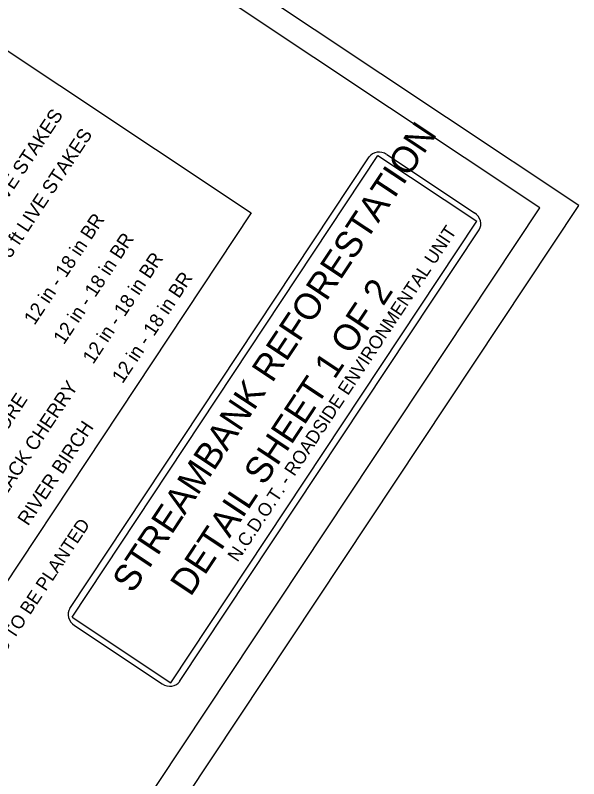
# Model space of a CAD drawing. Extents: x 561231 to 564935, y 589159 to 602519.
# Drawn here: x 564689.6 to 564935, y 589750.5 to 590082.6 of the extents above; entities that cross this region are included whole.
import ezdxf

# ---------------------------------------------------------------- set-up
doc = ezdxf.new("R2010")
doc.units = 0
doc.layers.add('Old_Level_1', color=7, linetype='Continuous')
doc.layers.add('Sheet Plot Border Outside CELL', color=7, linetype='Continuous')

msp = doc.modelspace()

# ---------------------------------------------------------------- linework, layer by layer
at = {"layer": 'Old_Level_1'}
for p, q in [((564713.43, 589824.47), (564843.78, 590021.03)), ((564714.42, 589820.79), (564847.56, 590021.55)), ((564847.56, 590021.55), (564890.57, 589993.01)), ((564851.35, 590022.07), (564889.58, 589996.7)), ((564757.43, 589792.25), (564890.57, 589993.01)), ((564761.21, 589792.77), (564891.57, 589989.32)), ((564714.42, 589820.79), (564757.43, 589792.25)), ((564715.41, 589817.1), (564753.64, 589791.73))]:
    msp.add_line(p, q, dxfattribs=at)
for points in [[(564393.35, 590347.54), (563895.29, 589597.92), (564420.03, 589249.27), (564918.09, 589998.9)], [(564487.49, 589808.73), (564667.22, 590079.74), (564792.37, 589996.71), (564612.64, 589725.7)]]:
    msp.add_lwpolyline(points, close=True, dxfattribs=at)
for centre, major_axis, start_param, end_param in [((564848.56, 590017.86), (-4.78, 3.17), 4.713138, 6.283935), ((564886.79, 589992.49), (-4.78, 3.17), 3.142342, 4.713138), ((564718.2, 589821.3), (-4.78, 3.17), 0.000749, 1.571546), ((564756.44, 589795.94), (4.78, -3.17), 4.713138, 6.283935)]:
    msp.add_ellipse(centre, major_axis=major_axis, ratio=0.880425, start_param=start_param, end_param=end_param, dxfattribs=at)
at = {"layer": 'Sheet Plot Border Outside CELL'}
msp.add_lwpolyline([(564375.99, 589158.59), (564934.98, 589999.92), (564387.75, 590363.51), (563828.77, 589522.18)], close=True, dxfattribs=at)

# ---------------------------------------------------------------- texts
at = {"layer": 'Old_Level_1'}
for s, height, rotation, p in [('2 ft - 3 ft LIVE STAKES', 6.0385, 56.4482, (564664.54, 589969.7)), ('STREAMBANK REFORESTATION', 11.4695, 56.4482, (564740.74, 589830.7)), ('2 ft - 3 ft LIVE STAKES', 6.0385, 56.4482, (564677.32, 589961.23)), ('12 in - 18 in BR', 6.0385, 56.4482, (564698.01, 589947.46)), ('N.C.D.O.T. - ROADSIDE ENVIRONMENTAL UNIT', 5.735, 56.4482, (564786.42, 589844.43)), ('12 in - 18 in BR', 6.0385, 56.4482, (564710.79, 589938.99)), ('12 in - 18 in BR', 6.0385, 56.4482, (564723.56, 589930.51)), ('12 in - 18 in BR', 6.0385, 56.4482, (564736.34, 589922.04)), ('   DETAIL SHEET 1 OF 2', 11.4695, 56.4482, (564758.91, 589818.66)), ('BLACK CHERRY', 6.0385, 56.3995, (564682.43, 589868.61)), ('SYCAMORE', 6.039, 56.3995, (564669.67, 589877.1)), ('RIVER BIRCH', 6.0385, 56.3995, (564695.2, 589860.13)), ('SEE PLAN SHEETS FOR AREAS TO BE PLANTED', 5.735, 56.4482, (564623.27, 589711.67))]:
    msp.add_text(s, height=height, rotation=rotation, dxfattribs=at).set_placement(p)

doc.saveas('drawing.dxf')
